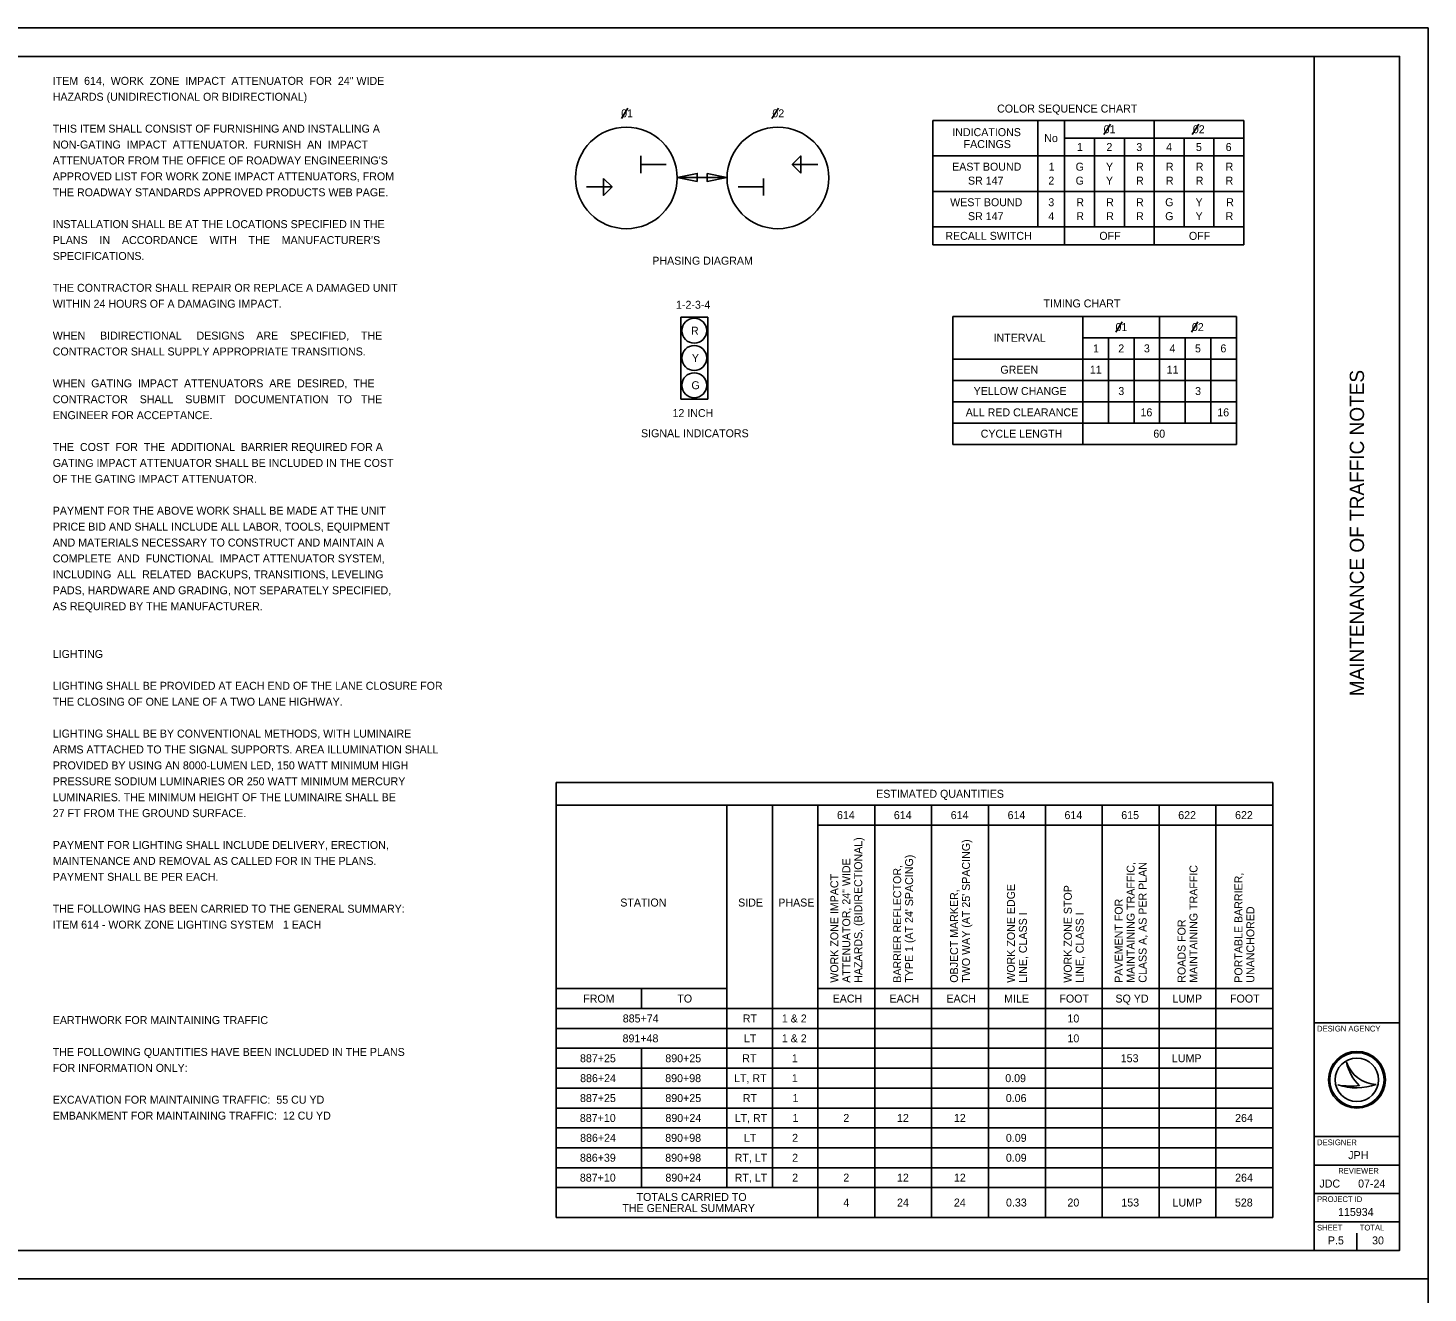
# Model space of a CAD drawing. Extents: x -214 to 680, y -440 to 880.
# Drawn here: x 187.7 to 680, y 435 to 880 of the extents above; entities that cross this region are included whole.
import ezdxf

# ---------------------------------------------------------------- set-up
doc = ezdxf.new("R2010")
doc.units = 0
for name, color, linetype in [('Default', 7, 'Continuous'), ('DR_X_Culvert', 7, 'Continuous'), ('PF_P_Grade_Line', 7, 'Continuous'), ('PF_X_Ground_Line', 7, 'Continuous'), ('PV_P_EOP', 7, 'Continuous'), ('PV_P_Shoulder', 7, 'Continuous'), ('TX_P_1', 7, 'Continuous'), ('XS_X_Pavt', 7, 'Continuous')]:
    doc.layers.add(name, color=color, linetype=linetype)

msp = doc.modelspace()

# ---------------------------------------------------------------- linework, layer by layer
at = {"layer": 'Default'}
for p, q in [((505.84, 847.51), (505.84, 803.76)), ((505.84, 847.51), (615.22, 847.51)), ((542.84, 847.51), (542.84, 810.01)), ((552.22, 847.51), (552.22, 803.76)), ((583.72, 847.51), (583.72, 803.76)), ((615.22, 847.51), (615.22, 803.76)), ((615.22, 847.51), (615.22, 803.76)), ((552.22, 841.26), (615.22, 841.26)), ((562.72, 841.26), (562.72, 810.01)), ((573.22, 841.26), (573.22, 810.01)), ((594.22, 841.26), (594.22, 810.01)), ((604.72, 841.26), (604.72, 810.01)), ((505.84, 835.01), (615.22, 835.01)), ((505.84, 822.51), (615.22, 822.51)), ((505.84, 810.01), (615.22, 810.01)), ((505.84, 803.76), (615.22, 803.76)), ((426.78, 778.25), (417.21, 778.25)), ((417.21, 778.25), (417.21, 749.41)), ((426.78, 749.41), (426.78, 778.25)), ((512.92, 778.54), (612.64, 778.54)), ((512.92, 778.54), (512.92, 733.54)), ((558.64, 778.54), (558.64, 733.54)), ((585.64, 778.54), (585.64, 741.04)), ((612.64, 778.54), (612.64, 733.54)), ((558.64, 771.04), (612.64, 771.04)), ((567.64, 771.04), (567.64, 741.04)), ((576.64, 771.04), (576.64, 741.04)), ((594.64, 771.04), (594.64, 741.04)), ((603.64, 771.04), (603.64, 741.04)), ((512.92, 763.54), (612.64, 763.54)), ((512.92, 756.04), (612.64, 756.04)), ((417.21, 749.41), (426.78, 749.41)), ((512.92, 748.54), (612.64, 748.54)), ((512.92, 741.04), (612.64, 741.04)), ((512.92, 733.54), (612.64, 733.54))]:
    msp.add_line(p, q, dxfattribs=at)
for centre in [(421.98, 773.52), (421.98, 763.91), (421.98, 754.33)]:
    msp.add_circle(centre, 4.39, dxfattribs=at)
at = {"layer": 'DR_X_Culvert'}
for points in [[(0, 440), (680, 440), (680, 880), (0, 880)], [(0, 0), (680, 0), (680, 440), (0, 440)]]:
    msp.add_lwpolyline(points, close=True, dxfattribs=at)
at = {"layer": 'PF_P_Grade_Line'}
for p, q in [((566.03, 842.55), (568.33, 846.18)), ((597.12, 842.55), (599.43, 846.18)), ((570.2, 772.96), (572.5, 776.59)), ((596.79, 772.96), (599.09, 776.59)), ((373.44, 461.58), (373.44, 614.61)), ((373.44, 614.61), (625.44, 614.61)), ((625.44, 461.58), (625.44, 614.61)), ((373.44, 606.61), (625.44, 606.61)), ((433.44, 472.08), (433.44, 606.61)), ((449.44, 472.08), (449.44, 606.61)), ((465.44, 461.58), (465.44, 606.61)), ((485.44, 461.58), (485.44, 606.61)), ((505.44, 461.58), (505.44, 606.61)), ((525.44, 461.58), (525.44, 606.61)), ((545.44, 461.58), (545.44, 606.61)), ((565.44, 461.58), (565.44, 606.61)), ((585.44, 461.58), (585.44, 606.61)), ((605.44, 461.58), (605.44, 606.61)), ((465.44, 599.61), (625.44, 599.61)), ((403.44, 535.08), (403.44, 542.08)), ((465.44, 542.08), (625.44, 542.08)), ((373.44, 535.08), (625.44, 535.08)), ((373.44, 528.08), (625.44, 528.08)), ((373.44, 521.08), (625.44, 521.08)), ((403.44, 472.08), (403.44, 521.08)), ((373.44, 514.08), (625.44, 514.08)), ((373.44, 507.08), (625.44, 507.08)), ((373.44, 500.08), (625.44, 500.08)), ((373.44, 493.08), (625.44, 493.08)), ((373.44, 486.08), (625.44, 486.08)), ((373.44, 479.08), (625.44, 479.08)), ((373.44, 472.08), (625.44, 472.08)), ((373.44, 461.58), (625.44, 461.58))]:
    msp.add_line(p, q, dxfattribs=at)
at = {"layer": 'PF_X_Ground_Line'}
for p, q in [((433.49, 827.44), (416.02, 827.44)), ((651.35, 516.19), (651.35, 516.19)), ((648.34, 508.19), (648.34, 508.19)), ((655, 510), (655, 510)), ((661.75, 508.37), (661.75, 508.37)), ((647.5, 453.5), (647.5, 453.5)), ((655, 450), (655, 456))]:
    msp.add_line(p, q, dxfattribs=at)
for centre, radius in [((398.12, 827.27), 17.87), ((451.39, 827.27), 17.87), ((655, 510), 10), ((655, 510), 9.54), ((655, 510), 9.54), ((655, 510), 7.64)]:
    msp.add_circle(centre, radius, dxfattribs=at)
for centre, radius, start, end in [((662.32, 519.95), 11.6, 198.9257, 198.9319), ((666.93, 519.4), 15.91, 191.6379, 191.6421), ((662.32, 519.95), 11.6, 198.9319, 267.1657), ((666.93, 519.4), 15.91, 191.6421, 226.0947), ((654.79, 527.4), 20.26, 251.4576, 290.0832), ((652.96, 533.09), 25.32, 259.4964, 259.4995), ((654.79, 527.4), 20.26, 251.4527, 251.4576), ((652.96, 533.09), 25.32, 259.4995, 276.6672)]:
    msp.add_arc(centre, radius, start, end, dxfattribs=at)
at = {"layer": 'PV_P_EOP'}
for p, q in [((403.15, 834.98), (403.15, 828.98)), ((412.16, 831.97), (403.15, 831.97)), ((446.38, 821.09), (446.38, 827.09)), ((465.43, 831.97), (456.42, 831.97)), ((384.09, 824.1), (393.1, 824.1)), ((437.37, 824.1), (446.38, 824.1))]:
    msp.add_line(p, q, dxfattribs=at)
for points in [[(459.42, 828.97), (456.42, 831.97), (459.42, 834.97)], [(390.1, 827.1), (393.1, 824.1), (390.1, 821.1)], [(423.02, 826.04), (416.02, 827.44), (423.02, 828.84)], [(426.49, 828.84), (433.49, 827.44), (426.49, 826.04)]]:
    msp.add_lwpolyline(points, close=True, dxfattribs=at)
at = {"layer": 'PV_P_Shoulder'}
for p, q in [((396.38, 848.15), (398.68, 851.78)), ((449.27, 848.15), (451.57, 851.78))]:
    msp.add_line(p, q, dxfattribs=at)
at = {"layer": 'TX_P_1'}
for p, q in [((640, 450), (640, 870)), ((640, 530), (670, 530)), ((640, 490), (670, 490)), ((640, 480), (670, 480)), ((640, 470), (670, 470)), ((640, 460), (670, 460))]:
    msp.add_line(p, q, dxfattribs=at)
msp.add_lwpolyline([(30, 870), (670, 870), (670, 450), (30, 450)], close=True, dxfattribs=at)
at = {"layer": 'XS_X_Pavt'}
msp.add_line((433.44, 542.08), (373.44, 542.08), dxfattribs=at)

# ---------------------------------------------------------------- texts
at = {"layer": 'Default'}
for s, p in [('COLOR SEQUENCE CHART', (528.48, 850.26)), ('TIMING CHART', (544.8, 781.71)), ('R', (420.83, 772.12)), ('Y', (421.13, 762.52)), ('G', (421, 752.93)), ('SIGNAL INDICATORS', (403.26, 736.03))]:
    msp.add_text(s, height=2.8, dxfattribs=at).set_placement(p)
at = {"layer": 'PF_P_Grade_Line'}
for s, p in [('01', (396.28, 848.58)), ('02', (449.45, 848.58)), ('INDICATIONS', (512.71, 841.96)), ('No', (545.06, 839.86)), ('01', (565.94, 842.98)), ('02', (597.31, 842.98)), ('FACINGS', (516.7, 837.76)), ('1', (556.55, 836.73)), ('2', (566.92, 836.73)), ('3', (577.43, 836.73)), ('4', (587.93, 836.73)), ('5', (598.4, 836.73)), ('6', (608.85, 836.73)), ('EAST BOUND', (512.66, 829.81)), ('1', (546.62, 829.81)), ('G', (556.09, 829.81)), ('Y', (566.75, 829.81)), ('R', (577.33, 829.81)), ('R', (587.83, 829.81)), ('R', (598.33, 829.81)), ('R', (608.83, 829.81)), ('SR 147', (518.23, 824.91)), ('2', (546.49, 824.91)), ('G', (556.09, 824.91)), ('Y', (566.75, 824.91)), ('R', (577.33, 824.91)), ('R', (587.83, 824.91)), ('R', (598.33, 824.91)), ('R', (608.83, 824.91)), ('WEST BOUND', (511.97, 817.31)), ('3', (546.49, 817.31)), ('R', (556.33, 817.31)), ('R', (566.83, 817.31)), ('R', (577.33, 817.31)), ('G', (587.59, 817.31)), ('Y', (598.25, 817.31)), ('R', (609.05, 817.31)), ('SR 147', (518.23, 812.41)), ('4', (546.49, 812.41)), ('R', (556.33, 812.41)), ('R', (566.83, 812.41)), ('R', (577.33, 812.41)), ('G', (587.59, 812.41)), ('Y', (598.25, 812.41)), ('R', (608.83, 812.41)), ('RECALL SWITCH', (510.27, 805.48)), ('OFF', (564.43, 805.48)), ('OFF', (595.93, 805.48)), ('1-2-3-4', (415.57, 781.24)), ('01', (570.1, 773.39)), ('02', (596.97, 773.39)), ('INTERVAL', (527.24, 769.64)), ('1', (562.22, 765.89)), ('2', (571.09, 765.89)), ('3', (580.1, 765.89)), ('4', (589.1, 765.89)), ('5', (598.07, 765.89)), ('6', (607.01, 765.89)), ('GREEN', (529.62, 758.39)), ('11', (561.1, 758.39)), ('11', (588.1, 758.39)), ('YELLOW CHANGE', (520.23, 750.89)), ('3', (571.1, 750.89)), ('3', (598.1, 750.89)), ('12 INCH', (414.33, 743.14)), ('ALL RED CLEARANCE', (517.45, 743.39)), ('16', (578.9, 743.39)), ('16', (605.9, 743.39)), ('CYCLE LENGTH', (522.71, 735.89)), ('60', (583.41, 735.89)), ('ESTIMATED QUANTITIES', (485.95, 609.21)), ('614', (472.17, 601.71)), ('614', (492.17, 601.71)), ('614', (512.17, 601.71)), ('614', (532.17, 601.71)), ('614', (552.17, 601.71)), ('615', (572.14, 601.71)), ('622', (592.16, 601.71)), ('622', (612.16, 601.71)), ('STATION', (395.97, 570.96)), ('SIDE', (437.42, 570.96)), ('PHASE', (451.54, 570.96)), ('FROM', (382.94, 537.18)), ('TO', (416.03, 537.18)), ('EACH', (470.65, 537.18)), ('EACH', (490.65, 537.18)), ('EACH', (510.65, 537.18)), ('MILE', (530.96, 537.18)), ('FOOT', (550.39, 537.18)), ('SQ YD', (570.09, 537.18)), ('LUMP', (590.16, 537.18)), ('FOOT', (610.39, 537.18)), ('885+74', (396.84, 530.18)), ('RT', (439.07, 530.18)), ('1 & 2', (452.78, 530.18)), ('10', (553.21, 530.18)), ('891+48', (396.78, 523.18)), ('LT', (439.46, 523.18)), ('1 & 2', (452.78, 523.18)), ('10', (553.21, 523.18)), ('887+25', (381.81, 516.18)), ('890+25', (411.81, 516.18)), ('RT', (438.86, 516.18)), ('1', (456.31, 516.18)), ('153', (571.96, 516.18)), ('LUMP', (589.95, 516.18)), ('886+24', (381.84, 509.18)), ('890+98', (411.78, 509.18)), ('0.09', (531.35, 509.18)), ('LT, RT', (435.98, 509.18)), ('1', (456.31, 509.18)), ('887+25', (381.81, 502.18)), ('890+25', (411.81, 502.18)), ('RT', (439.07, 502.18)), ('1', (456.53, 502.18)), ('0.06', (531.53, 502.18)), ('887+10', (381.76, 495.18)), ('890+24', (411.84, 495.18)), ('LT, RT', (436.19, 495.18)), ('1', (456.53, 495.18)), ('2', (474.4, 495.18)), ('12', (493.28, 495.18)), ('12', (513.28, 495.18)), ('264', (612.17, 495.18)), ('886+24', (381.84, 488.18)), ('890+98', (411.78, 488.18)), ('LT', (439.46, 488.18)), ('2', (456.4, 488.18)), ('0.09', (531.57, 488.18)), ('886+39', (381.79, 481.18)), ('890+98', (411.78, 481.18)), ('RT, LT', (436.19, 481.18)), ('2', (456.4, 481.18)), ('0.09', (531.57, 481.18)), ('887+10', (381.76, 474.18)), ('890+24', (411.84, 474.18)), ('RT, LT', (436.19, 474.18)), ('2', (456.4, 474.18)), ('2', (474.4, 474.18)), ('12', (493.28, 474.18)), ('12', (513.28, 474.18)), ('264', (612.17, 474.18)), ('TOTALS CARRIED TO', (401.7, 467.38)), ('4', (474.41, 465.43)), ('24', (493.29, 465.43)), ('24', (513.29, 465.43)), ('0.33', (531.61, 465.43)), ('20', (553.21, 465.43)), ('153', (572.17, 465.43)), ('LUMP', (590.16, 465.43)), ('528', (612.11, 465.43)), ('THE GENERAL SUMMARY', (396.72, 463.48))]:
    msp.add_text(s, height=2.8, dxfattribs=at).set_placement(p)
for s, p in [('HAZARDS, (BIDIRECTIONAL)', (481.04, 544.15)), ("TWO WAY (AT 25' SPACING)", (518.94, 544.15)), ('ATTENUATOR, 24" WIDE', (476.84, 544.15)), ("TYPE 1 (AT 24' SPACING)", (498.94, 544.15)), ('MAINTAINING TRAFFIC,', (576.84, 544.15)), ('CLASS A, AS PER PLAN', (581.04, 544.15)), ('WORK ZONE IMPACT', (472.64, 544.15)), ('BARRIER REFLECTOR,', (494.74, 544.15)), ('MAINTAINING TRAFFIC', (598.94, 544.15)), ('PORTABLE BARRIER,', (614.74, 544.15)), ('OBJECT MARKER,', (514.74, 544.15)), ('WORK ZONE EDGE', (534.74, 544.15)), ('WORK ZONE STOP', (554.74, 544.15)), ('PAVEMENT FOR', (572.64, 544.15)), ('LINE, CLASS I', (538.94, 544.15)), ('LINE, CLASS I', (558.94, 544.15)), ('ROADS FOR', (594.74, 544.15)), ('UNANCHORED', (618.94, 544.15))]:
    msp.add_text(s, height=2.8, rotation=90, dxfattribs=at).set_placement(p)
at = {"layer": 'PF_X_Ground_Line'}
msp.add_text('MAINTENANCE OF TRAFFIC NOTES', height=5, rotation=90, dxfattribs=at).set_placement((657.5, 644.93))
for s, height, p in [('DESIGN AGENCY', 2, (641, 527)), ('DESIGNER', 2, (641, 487)), ('JPH', 2.8, (651.97, 482.1)), ('REVIEWER', 2, (648.44, 477)), ('JDC', 2.8, (641.82, 472.1)), ('07-24', 2.8, (655.42, 472.1)), ('PROJECT ID', 2, (641, 467)), ('115934', 2.8, (648.36, 462.1)), ('SHEET', 2, (641, 457)), ('TOTAL', 2, (656, 457)), ('P.5', 2.8, (644.81, 452.1)), ('30', 2.8, (660.34, 452.1))]:
    msp.add_text(s, height=height, dxfattribs=at).set_placement(p)
at = {"layer": 'PV_P_Shoulder'}
msp.add_text('PHASING DIAGRAM', height=2.8, dxfattribs=at).set_placement((407.23, 796.74))
at = {"layer": 'XS_X_Pavt'}
for s, p in [('ITEM  614,  WORK  ZONE  IMPACT  ATTENUATOR  FOR  24" WIDE', (196.4, 860)), ('HAZARDS (UNIDIRECTIONAL OR BIDIRECTIONAL)', (196.4, 854.4)), ('THIS ITEM SHALL CONSIST OF FURNISHING AND INSTALLING A', (196.4, 843.2)), ('NON-GATING  IMPACT  ATTENUATOR.  FURNISH  AN  IMPACT', (196.4, 837.6)), ("ATTENUATOR FROM THE OFFICE OF ROADWAY ENGINEERING'S", (196.4, 832)), ('APPROVED LIST FOR WORK ZONE IMPACT ATTENUATORS, FROM', (196.4, 826.4)), ('THE ROADWAY STANDARDS APPROVED PRODUCTS WEB PAGE.', (196.4, 820.8)), ('INSTALLATION SHALL BE AT THE LOCATIONS SPECIFIED IN THE', (196.4, 809.6)), ("PLANS    IN    ACCORDANCE    WITH    THE    MANUFACTURER'S", (196.4, 804)), ('SPECIFICATIONS.', (196.4, 798.4)), ('THE CONTRACTOR SHALL REPAIR OR REPLACE A DAMAGED UNIT', (196.4, 787.2)), ('WITHIN 24 HOURS OF A DAMAGING IMPACT.', (196.4, 781.6)), ('WHEN     BIDIRECTIONAL     DESIGNS    ARE    SPECIFIED,    THE', (196.4, 770.4)), ('CONTRACTOR SHALL SUPPLY APPROPRIATE TRANSITIONS.', (196.4, 764.8)), ('WHEN  GATING  IMPACT  ATTENUATORS  ARE  DESIRED,  THE', (196.4, 753.6)), ('CONTRACTOR    SHALL    SUBMIT   DOCUMENTATION   TO   THE', (196.4, 748)), ('ENGINEER FOR ACCEPTANCE.', (196.4, 742.4)), ('THE  COST  FOR  THE  ADDITIONAL  BARRIER REQUIRED FOR A', (196.4, 731.2)), ('GATING IMPACT ATTENUATOR SHALL BE INCLUDED IN THE COST', (196.4, 725.6)), ('OF THE GATING IMPACT ATTENUATOR.', (196.4, 720)), ('PAYMENT FOR THE ABOVE WORK SHALL BE MADE AT THE UNIT', (196.4, 708.8)), ('PRICE BID AND SHALL INCLUDE ALL LABOR, TOOLS, EQUIPMENT', (196.4, 703.2)), ('AND MATERIALS NECESSARY TO CONSTRUCT AND MAINTAIN A', (196.4, 697.6)), ('COMPLETE  AND  FUNCTIONAL  IMPACT ATTENUATOR SYSTEM,', (196.4, 692)), ('INCLUDING  ALL  RELATED  BACKUPS, TRANSITIONS, LEVELING', (196.4, 686.4)), ('PADS, HARDWARE AND GRADING, NOT SEPARATELY SPECIFIED,', (196.4, 680.8)), ('AS REQUIRED BY THE MANUFACTURER.', (196.4, 675.2)), ('LIGHTING', (196.4, 658.4)), ('LIGHTING SHALL BE PROVIDED AT EACH END OF THE LANE CLOSURE FOR', (196.4, 647.2)), ('THE CLOSING OF ONE LANE OF A TWO LANE HIGHWAY.', (196.4, 641.6)), ('LIGHTING SHALL BE BY CONVENTIONAL METHODS, WITH LUMINAIRE', (196.4, 630.4)), ('ARMS ATTACHED TO THE SIGNAL SUPPORTS. AREA ILLUMINATION SHALL', (196.4, 624.8)), ('PROVIDED BY USING AN 8000-LUMEN LED, 150 WATT MINIMUM HIGH', (196.4, 619.2)), ('PRESSURE SODIUM LUMINARIES OR 250 WATT MINIMUM MERCURY', (196.4, 613.6)), ('LUMINARIES. THE MINIMUM HEIGHT OF THE LUMINAIRE SHALL BE', (196.4, 608)), ('27 FT FROM THE GROUND SURFACE.', (196.4, 602.4)), ('PAYMENT FOR LIGHTING SHALL INCLUDE DELIVERY, ERECTION,', (196.4, 591.2)), ('MAINTENANCE AND REMOVAL AS CALLED FOR IN THE PLANS.', (196.4, 585.6)), ('PAYMENT SHALL BE PER EACH.', (196.4, 580)), ('THE FOLLOWING HAS BEEN CARRIED TO THE GENERAL SUMMARY:', (196.4, 568.8)), ('ITEM 614 - WORK ZONE LIGHTING SYSTEM   1 EACH', (196.4, 563.2)), ('EARTHWORK FOR MAINTAINING TRAFFIC', (196.4, 529.6)), ('THE FOLLOWING QUANTITIES HAVE BEEN INCLUDED IN THE PLANS', (196.4, 518.4)), ('FOR INFORMATION ONLY:', (196.4, 512.8)), ('EXCAVATION FOR MAINTAINING TRAFFIC:  55 CU YD', (196.4, 501.6)), ('EMBANKMENT FOR MAINTAINING TRAFFIC:  12 CU YD ', (196.4, 496))]:
    msp.add_text(s, height=2.8, dxfattribs=at).set_placement(p)

doc.saveas('drawing.dxf')
